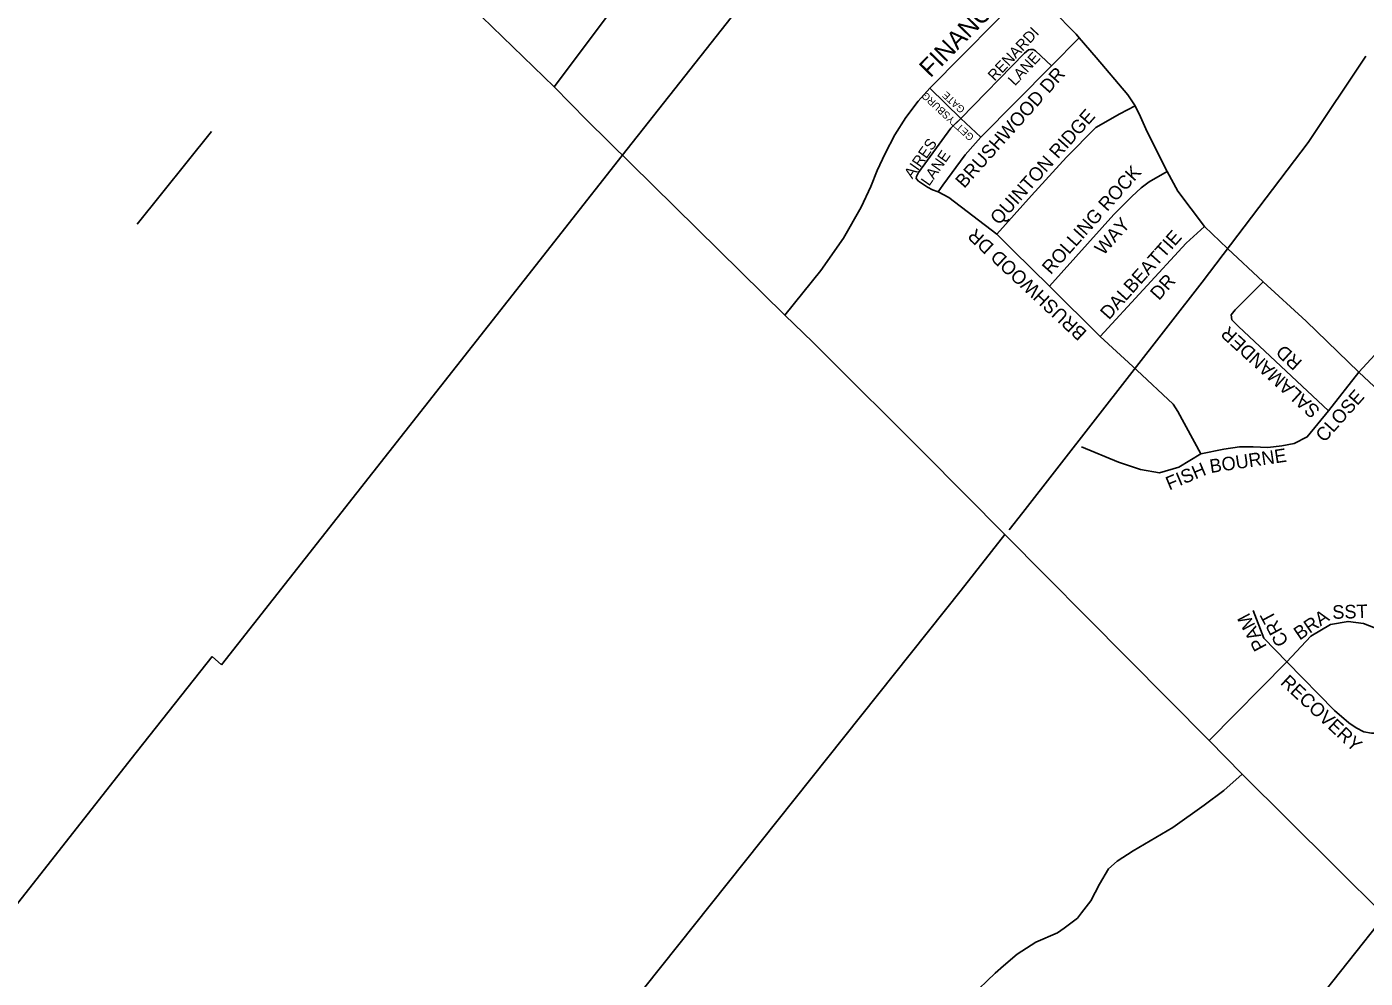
# Model space of a CAD drawing. Extents: x 586326 to 623965, y 4819854 to 4857850.
# Drawn here: x 595945 to 597455, y 4830499 to 4831572 of the extents above; entities that cross this region are included whole.
import ezdxf

# ---------------------------------------------------------------- set-up
doc = ezdxf.new("R2010")
doc.units = 0
for name, color, linetype in [('Lots_Concessions', 7, 'Continuous'), ('Major Rds and Hwys', 7, 'Continuous'), ('Private Rds', 7, 'Continuous'), ('Proposed Minor Rds', 7, 'Continuous'), ('Proposed Rd Lbls', 7, 'Continuous'), ('Proposed Secondary Rds', 7, 'Continuous')]:
    doc.layers.add(name, color=color, linetype=linetype)

msp = doc.modelspace()

# ---------------------------------------------------------------- linework, layer by layer
at = {"layer": 'Lots_Concessions'}
for p, q in [((596616.5, 4831426.8), (597031.4, 4831952.5)), ((597390.4, 4831441.5), (597455.3, 4831539.2)), ((596069.5, 4831349.5), (596153.4, 4831454.1)), ((597270.7, 4831284.2), (597390.4, 4831441.5)), ((596551.6, 4831344.2), (596616.7, 4831426.9)), ((596524, 4831309.1), (596551.6, 4831344.2)), ((596164.7, 4830852.5), (596524, 4831309.1)), ((597068.6, 4831024.4), (597270.7, 4831284.2)), ((597053, 4831004.8), (597068.6, 4831024.4)), ((596998.8, 4830936.6), (597048.3, 4830999.5)), ((596591, 4830424.6), (596998.8, 4830936.6)), ((596062.8, 4830746.2), (596153.9, 4830861.7)), ((596153.9, 4830861.7), (596164.7, 4830852.5)), ((595891.8, 4830529.1), (596062.8, 4830746.2)), ((597375.3, 4830441.7), (597477.4, 4830570.1))]:
    msp.add_line(p, q, dxfattribs=at)
at = {"layer": 'Major Rds and Hwys'}
for points in [[(596539.8, 4831504.4), (596458.2, 4831583.4), (596182.6, 4831854.7), (596086, 4831949.9)], [(596576.5, 4831466.8), (596539.8, 4831504.4)], [(596800.1, 4831247), (596576.5, 4831466.8)], [(596831.5, 4831216.5), (596800.1, 4831247)], [(596956.3, 4831092), (596841.1, 4831206.9), (596831.5, 4831216.5)], [(597278.6, 4830767.1), (596956.3, 4831092)], [(597315.8, 4830729.2), (597278.6, 4830767.1)], [(597419.3, 4830626.3), (597315.8, 4830729.2)], [(597901.1, 4830113.7), (597843.7, 4830167.7), (597799.9, 4830209.6), (597778.6, 4830231.3), (597720.5, 4830310.4), (597670.7, 4830370.2), (597622.4, 4830424.4), (597477.5, 4830568.5), (597419.3, 4830626.3)]]:
    msp.add_lwpolyline(points, dxfattribs=at)
at = {"layer": 'Private Rds'}
msp.add_lwpolyline([(597009.8, 4830478.3), (597037.2, 4830504.6), (597046.8, 4830512.7), (597062.3, 4830525.8), (597083.1, 4830539.4), (597107.6, 4830550), (597115.1, 4830555.5), (597130, 4830566.6), (597134.6, 4830572.6), (597145.2, 4830586.2), (597154.9, 4830605.1), (597165.1, 4830622.4), (597175.1, 4830631), (597192.8, 4830642.7), (597237.9, 4830668.8), (597273, 4830694.1), (597295.4, 4830710.7), (597315.8, 4830729.2)], dxfattribs=at)
at = {"layer": 'Proposed Minor Rds'}
for points in [[(596539.8, 4831504.4), (596605.8, 4831592), (596704, 4831720.9)], [(597100.8, 4831528), (597132, 4831559.9)], [(596998.6, 4831468.8), (597070.5, 4831542.5), (597074.9, 4831546.1), (597077, 4831546.5), (597080, 4831546.4), (597082.7, 4831545.1), (597100.8, 4831528)], [(597021.3, 4831447.8), (597100.8, 4831528)], [(596998.6, 4831468.8), (596963.7, 4831503)], [(597078.4, 4831381.7), (597117.6, 4831425.2), (597150.7, 4831458.5), (597177.8, 4831474.1), (597195.1, 4831482.9)], [(596972.9, 4831385.8), (596966.6, 4831388.4), (596961, 4831391.3), (596951, 4831398.1), (596948.3, 4831400.9), (596948.4, 4831403.4), (596951, 4831407.7), (596987.3, 4831457.9), (596998.6, 4831468.8)], [(597021.3, 4831447.8), (596998.6, 4831468.8)], [(596972.9, 4831385.8), (596978.1, 4831393.4), (597003.4, 4831427.7), (597015.2, 4831440.9), (597021.3, 4831447.8)], [(597098.6, 4831279.6), (597171.3, 4831360.6), (597191.3, 4831380.7), (597202, 4831390.4), (597211.1, 4831397.2), (597231.3, 4831408.9)], [(597039.2, 4831338.1), (596985.2, 4831379.6), (596972.9, 4831385.8)], [(597039.2, 4831338.1), (597078.4, 4831381.7)], [(597447.7, 4831182.5), (597506.3, 4831246), (597529.3, 4831273.7), (597533.3, 4831282.4), (597531.5, 4831287.7), (597527.6, 4831293.6), (597500.5, 4831318.5), (597495.7, 4831324.4), (597494.2, 4831329.9), (597497.2, 4831336.1), (597532.1, 4831378.1), (597538.2, 4831381.3), (597543.7, 4831380.8), (597548.1, 4831377.5), (597642.7, 4831285.9)], [(597057.7, 4831319.9), (597039.2, 4831338.1)], [(597273.3, 4831346.8), (597252.7, 4831328.2), (597155.9, 4831222.8)], [(597098.6, 4831279.6), (597057.7, 4831319.9)], [(597155.9, 4831222.8), (597098.6, 4831279.6)], [(597413.3, 4831138.8), (597311.7, 4831234), (597304.4, 4831241.6), (597303.5, 4831247.3), (597308.1, 4831253), (597339.5, 4831284.4)], [(597197.1, 4831184.7), (597155.9, 4831222.8)], [(597269.5, 4831090.3), (597243.3, 4831138.3), (597238, 4831146.6), (597197.1, 4831184.7)], [(597413.3, 4831138.8), (597447.7, 4831182.5)], [(597269.5, 4831090.3), (597295.3, 4831095.8), (597312.8, 4831098.5), (597328.4, 4831098.5), (597345, 4831097.6), (597360.7, 4831099.5), (597374.5, 4831102.2), (597389.3, 4831109.6), (597413.3, 4831138.8)], [(597134.7, 4831098.3), (597176.4, 4831081), (597201.3, 4831072.7), (597222.5, 4831069.1), (597244.6, 4831075.5), (597269.5, 4831090.3)], [(597366.5, 4830855.6), (597340.5, 4830882.5), (597328.3, 4830913.8)], [(597366.5, 4830855.6), (597393.4, 4830884.6), (597415.4, 4830897.8), (597435.4, 4830901.4), (597452.9, 4830899.1), (597473.2, 4830891), (597487.7, 4830883), (597534.9, 4830866.1)], [(597278.6, 4830767.1), (597366.5, 4830855.6)], [(597534.9, 4830866.1), (597505.1, 4830790.1), (597501.8, 4830780.8), (597497.8, 4830776.5), (597490.7, 4830775), (597482, 4830774.8), (597469.6, 4830775.3), (597461.7, 4830775.4), (597453.2, 4830776.9), (597444.5, 4830781.2), (597436.3, 4830786.9), (597420.2, 4830801), (597366.5, 4830855.6)]]:
    msp.add_lwpolyline(points, dxfattribs=at)
at = {"layer": 'Proposed Secondary Rds'}
for points in [[(597074.4, 4831615.3), (596963.7, 4831503)], [(597132, 4831559.9), (597128.6, 4831563.9), (597101.2, 4831591.5), (597074.4, 4831615.3)], [(597195.1, 4831482.9), (597187, 4831495.5), (597151.3, 4831537.6), (597132, 4831559.9)], [(596963.7, 4831503), (596950.6, 4831488.2), (596936.7, 4831469.7), (596924, 4831450.3), (596913.2, 4831429.1), (596904.1, 4831409.9), (596897.1, 4831392), (596886.1, 4831368.8), (596866.2, 4831333.6), (596840.5, 4831297.4), (596800.1, 4831247)], [(597231.3, 4831408.9), (597208.7, 4831453.8), (597201.1, 4831470.7), (597195.1, 4831482.9)], [(597273.3, 4831346.8), (597243.4, 4831386.8), (597231.3, 4831408.9)], [(597299.5, 4831322.1), (597273.3, 4831346.8)], [(597339.5, 4831284.4), (597299.5, 4831322.1)], [(597388, 4831240.1), (597339.5, 4831284.4)], [(597447.7, 4831182.5), (597388, 4831240.1)], [(597498.7, 4831134.8), (597447.7, 4831182.5)]]:
    msp.add_lwpolyline(points, dxfattribs=at)

# ---------------------------------------------------------------- texts
at = {"layer": 'Proposed Rd Lbls'}
for s, height, rotation, p in [('FINANCIAL  DR ', 20.356, 45.658, (596964.2, 4831513.9)), ('RENARDI', 12.39, 46.9499, (597036.8, 4831510.2)), ('LANE', 12.39, 46.9499, (597059.6, 4831504.8)), ('BRUSHWOOD DR', 15.299, 48.3035, (597002.4, 4831389.2)), ('GETTYSBURG', 8.13, 137.412, (597014.1, 4831448.6)), ('GATE', 8.13, 137.412, (597004, 4831479.9)), ('QUINTON RIDGE', 15.299, 48.3035, (597041.6, 4831347.7)), ('AIRES', 12.39, 55.1175, (596943.8, 4831399.9)), ('LANE', 12.39, 55.1175, (596962.8, 4831391.7)), ('ROLLING ROCK', 15.299, 48.3035, (597100.1, 4831291.8)), ('WAY', 15.3, 48.3035, (597159.5, 4831313.5)), ('BRUSHWOOD DR', 15.299, 137.0788, (597141.8, 4831228.1)), ('DALBEATTIE', 15.3, 48.3035, (597165.7, 4831240.8)), ('DR', 15.3, 48.3035, (597222.1, 4831262.7)), ('SALAMANDER   ', 15.299, 137.6962, (597404.9, 4831140.5)), ('RD', 15.3, 137.6962, (597384.7, 4831194.7)), ('CLOSE', 15.3, 48.3035, (597408.7, 4831102.5)), ('BOURNE', 15.3, 8.5463, (597280.4, 4831068.7)), ('FISH', 15.3, 22.6983, (597233.7, 4831049.1)), ('BRA', 15.3, 34.1259, (597380.7, 4830879.6)), ('SST', 15.3, 1.4967, (597417.8, 4830904.2)), ('PAM', 15.3, 118.1568, (597344.1, 4830873)), (' CRT', 15.3, 118.1568, (597371.5, 4830873.1)), ('RECOVERY', 15.3, 317.0882, (597358.2, 4830831.3))]:
    msp.add_text(s, height=height, rotation=rotation, dxfattribs=at).set_placement(p)

doc.saveas('drawing.dxf')
